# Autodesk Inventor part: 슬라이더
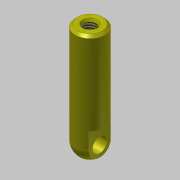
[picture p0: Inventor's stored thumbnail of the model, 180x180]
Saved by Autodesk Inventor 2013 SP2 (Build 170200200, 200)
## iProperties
Created: 2016-08
Part Number: 슬라이더
Material: 강철, 탄소
Document SubType Name: Modeling
Designer: mduedu
Density: 7.87 g/cm^3
Author: mduedu
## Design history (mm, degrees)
sketch "스케치1"
  geometry: C1 r 6 at (0, 0); 1 further point
  constraints: 1 centre point, 1 coincident
  dimensions: "d0" = 12 diameter of C1
extrude "돌출1" new body sketch "스케치1" distance "d1" = 47; taper "d2" = 0 deg
fillet "모깎기1" dims "d21" = 6
sketch "스케치6"
  geometry: L1 (6, 6)-(6, 47) reference; L2 (-6, 6)-(-6, 47) reference; L3 (6, 47)-(-6, 47) reference; L4 (0, 47)-(0, 0); L5 (6, 13)-(4, 13); L6 (4, 13)-(4, 0); L7 (4, 0)-(6, 0); L8 (6, 0)-(6, 13); L9 (-6, 13)-(-4, 13); L10 (-4, 13)-(-4, 0); L11 (-4, 0)-(-6, 0); L12 (-6, 0)-(-6, 13)
  constraints: 18 end point, 4 symmetric about line, 2 parallel, 2 perpendicular, 1 horizontal, 1 horizontal alignment, 1 midpoint, 1 point on line
  dimensions: "d22" = 13 distance of L7.end L5.start; "d24" = 4 distance between parallel lines of L6 L4
extrude "돌출5" cut sketch "스케치6" stored distance "d25" = 8; taper "d26" = 0 deg
sketch "스케치8"
  geometry: C1 r 3 at (6, 0); 1 further point
  constraints: 1 centre point, 1 horizontal alignment
  dimensions: "d27" = 6 diameter of C1; "d28" = 6 distance of point (0, 0) C1.centre
extrude "돌출6" cut sketch "스케치8" stored distance "d29" = 8; taper "d30" = 0 deg
hole "구멍1" diameter "d33" = 4.917; stored, may be unused: countersink angle "d37" = 90 deg, drill point angle "d39" = 118 deg; dims "d31" = 10, "d32" = 10, "d34" = 10, "d35" = 4, "d36" = 2, "d38" = 12
chamfer "모따기1" distance "d40" = 1; stored, may be unused: second distance "d41" = 2, angle "d42" = 30 deg
chamfer "모따기2" distance "d43" = 1; stored, may be unused: second distance "d44" = 2, angle "d45" = 30 deg
node "솔리드1"
